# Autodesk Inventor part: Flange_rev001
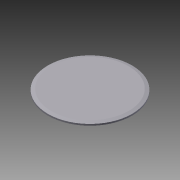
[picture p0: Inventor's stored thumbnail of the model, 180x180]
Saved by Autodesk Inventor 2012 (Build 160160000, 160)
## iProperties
Created: 2011-12
Part Number: Flange_rev001
Document SubType Name: Modeling
Designer: Alex
Density: 2.71 g/cm^3
Material: Aluminum-6061
Mass: 7.79956 g
Surface Area: 39.9297 cm^2
Volume: 2.87807 cm^3
Author: Alex
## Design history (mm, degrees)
sketch "Sketch1"
  geometry: L1 (0, 0)-(24.892, 0); L2 (24.892, 0)-(26.988, -0.601); L3 (0, -1.578)-(0, 0); L4 (26.988, -0.601)-(26.988, -1.578); L5 (0, -1.893)-(0, 0.316) reference; L6 (26.988, -1.578)-(0, -1.578); 1 further point
  constraints: 10 end point, 3 perpendicular, 2 point on line, 1 horizontal
  dimensions: "d1" = 24.892 distance of L1.end point (0, 0); "d2" = 164 deg angle of L2 L1; "d11" = 0.60087 vertical distance of L2.end L1.end (derived); "d12" = 1.57752 distance between parallel lines of L6 L1; "d13" = 2.0955 horizontal distance of L2.end L1.end; "d14" = 0.97664 distance of L4.end L2.end (derived); "d15" = 26.9875 distance from line of L4.end L3 (derived)
revolve "Revolution1" sketch "Sketch1" stored, may be unused: angle "d8" = 90 deg
body "Solid1"
